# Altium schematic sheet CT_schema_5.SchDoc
size 178 x 159 mm
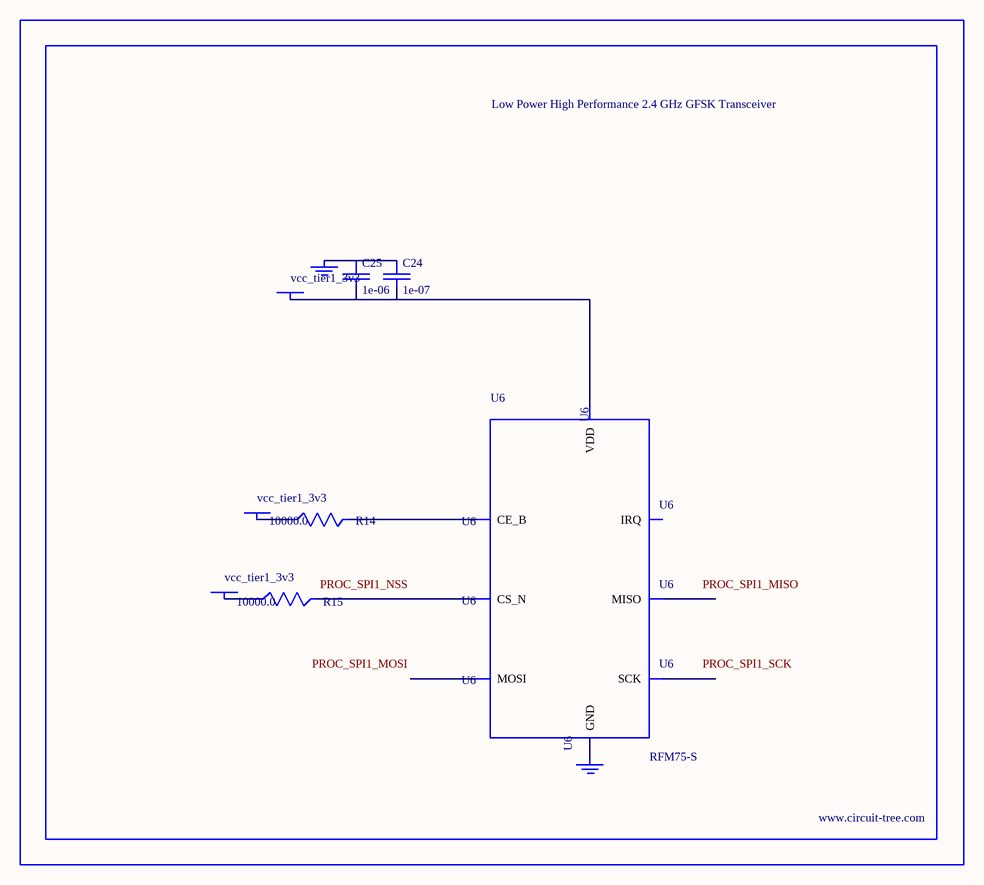
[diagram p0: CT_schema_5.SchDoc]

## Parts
BORDER4  (no value)
C24  1e-07  [C0402]
C25  1e-06  [C0603]
GND_INSTANCE_4_0  (no value)
GND_INSTANCE_4_1  (no value)
POWER_INSTANCE_4_0  vcc_tier1_3v3
POWER_INSTANCE_4_1  vcc_tier1_3v3
POWER_INSTANCE_4_2  vcc_tier1_3v3
R14  10000.0  [R0603]
R15  10000.0  [R0603]
U6  RFM75-S  [RFM75-S]

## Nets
NetC24_1: C24.1 C25.1 GND_INSTANCE_4_0.0(GND)
NetC24_2: C24.2 C25.2 POWER_INSTANCE_4_0.0(PWR) U6.2(VDD)
NetGND_INSTANCE_4_1_0: GND_INSTANCE_4_1.0(GND) U6.1(GND)
NetPOWER_INSTANCE_4_1_0: POWER_INSTANCE_4_1.0(PWR) R14.1
NetPOWER_INSTANCE_4_2_0: POWER_INSTANCE_4_2.0(PWR) R15.1
NetR14_2: R14.2 U6.3(CE_B)
NetR15_2: R15.2 U6.4(CS_N)

Not connected (* = marked no-connect by the designer): U6 5(SCK) 6(MOSI) 7(MISO) 8(IRQ)

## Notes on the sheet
- Labels drawn without touching a wire or pin: PROC_SPI1_MISO, PROC_SPI1_MOSI, PROC_SPI1_NSS, PROC_SPI1_SCK

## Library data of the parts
BORDER4 = BORDER_PAGE4
C24 = C0402C104K3RACTU
C25 = C0603C105K3RACTU
GND_INSTANCE_4_0 GND_INSTANCE_4_1 = GND
POWER_INSTANCE_4_0-POWER_INSTANCE_4_2 = PWR
R14 R15 = RC0603JR-0710KL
